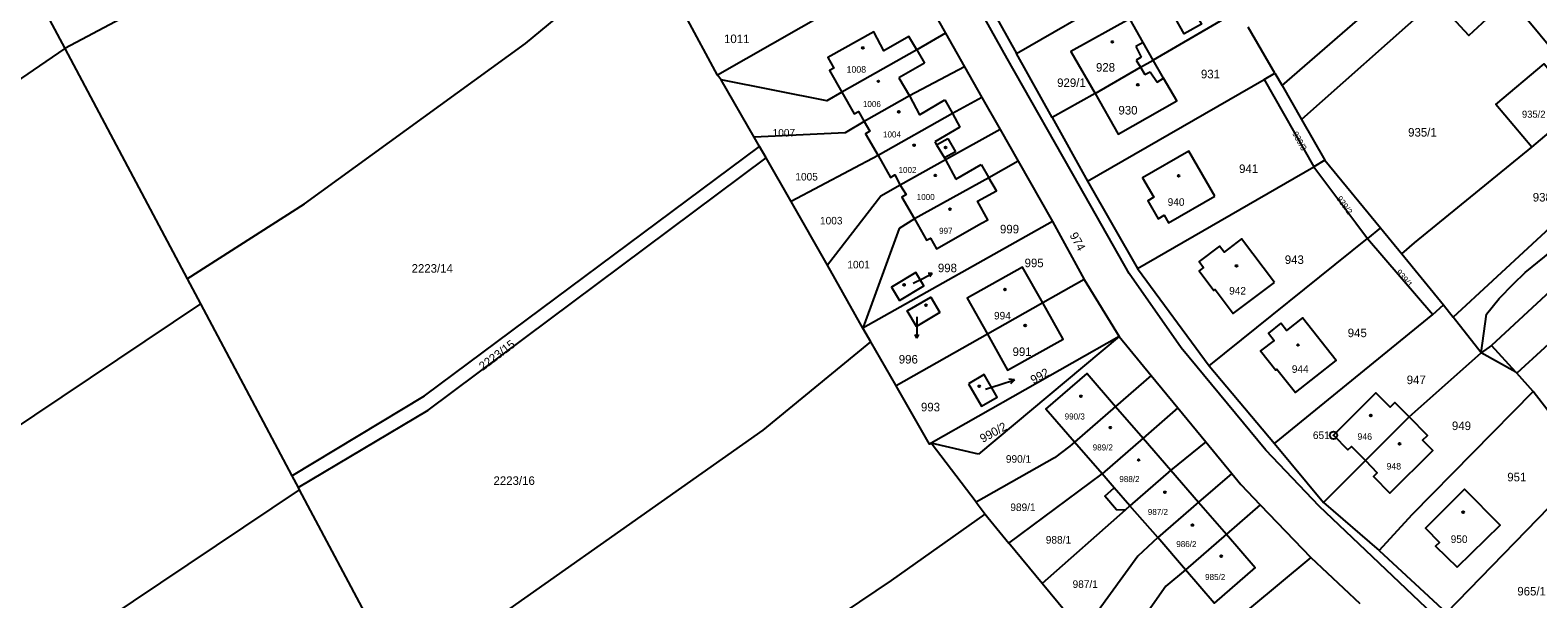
# Model space of a CAD drawing. Extents: x -504988 to -494607, y -1123820 to -1114018.
# Drawn here: x -497845.6 to -497545.8, y -1120241.9 to -1120128.9 of the extents above; entities that cross this region are included whole.
import ezdxf

# ---------------------------------------------------------------- set-up
doc = ezdxf.new("R2010")
doc.units = 0
for name, color, linetype in [('Hranice parcel', 7, 'Continuous'), ('Parcelní čísla', 7, 'Continuous'), ('Pop  PČ popisy', 7, 'Continuous'), ('Vnitřní kresba', 7, 'Continuous'), ('Značky bodu BP', 7, 'Continuous'), ('Značky budov', 7, 'Continuous')]:
    doc.layers.add(name, color=color, linetype=linetype)

msp = doc.modelspace()

# ---------------------------------------------------------------- linework, layer by layer
at = {"layer": 'Hranice parcel'}
for p, q in [((-497859.72, -1120093.09), (-497838.74, -1120132.52)), ((-497596.6, -1120139.88), (-497555.6, -1120104.26)), ((-497649.42, -1120133.52), (-497612.36, -1120112.05)), ((-497671.08, -1120116.23), (-497708.88, -1120137.79)), ((-497671.08, -1120116.23), (-497663.57, -1120129.44)), ((-497658.18, -1120117.79), (-497649.42, -1120133.52)), ((-497605.3, -1120124.94), (-497622.27, -1120134.79)), ((-497708.88, -1120137.79), (-497715.36, -1120125.87)), ((-497543.02, -1120132.55), (-497547.56, -1120127.17)), ((-497663.57, -1120129.44), (-497669.29, -1120132.77)), ((-497663.57, -1120129.44), (-497659.77, -1120136.14)), ((-497598.04, -1120137.4), (-497603.34, -1120128.29)), ((-497838.74, -1120132.52), (-497908.58, -1120180.24)), ((-497838.74, -1120132.52), (-497814.39, -1120178.27)), ((-497669.29, -1120132.77), (-497684.2, -1120141.18)), ((-497642.36, -1120146.19), (-497649.42, -1120133.52)), ((-497659.77, -1120136.14), (-497656.32, -1120142.22)), ((-497708.18, -1120138.71), (-497708.88, -1120137.79)), ((-497701.6, -1120150.15), (-497708.18, -1120138.71)), ((-497635.31, -1120158.85), (-497600.2, -1120138.64)), ((-497600.2, -1120138.64), (-497598.04, -1120137.4)), ((-497600.2, -1120138.64), (-497590.31, -1120156.01)), ((-497598.04, -1120137.4), (-497596.6, -1120139.88)), ((-497596.6, -1120139.88), (-497592.77, -1120146.58)), ((-497656.32, -1120142.22), (-497652.71, -1120148.57)), ((-497633.81, -1120141.47), (-497642.36, -1120146.19)), ((-497562.59, -1120185.87), (-497517.1, -1120143.77)), ((-497652.71, -1120148.57), (-497649.11, -1120154.91)), ((-497642.36, -1120146.19), (-497635.31, -1120158.85)), ((-497592.77, -1120146.58), (-497588.12, -1120154.71)), ((-497700.55, -1120151.98), (-497701.6, -1120150.15)), ((-497699.25, -1120154.24), (-497700.55, -1120151.98)), ((-497694.25, -1120162.93), (-497699.25, -1120154.24)), ((-497676.98, -1120153.77), (-497694.25, -1120162.93)), ((-497649.11, -1120154.91), (-497654.92, -1120158.19)), ((-497649.11, -1120154.91), (-497642.3, -1120166.91)), ((-497588.12, -1120154.71), (-497590.31, -1120156.01)), ((-497588.12, -1120154.71), (-497577.07, -1120168.16)), ((-497625.36, -1120176.21), (-497590.31, -1120156.01)), ((-497654.92, -1120158.19), (-497669.75, -1120166.36)), ((-497635.31, -1120158.85), (-497625.36, -1120176.21)), ((-497687.02, -1120175.53), (-497694.25, -1120162.93)), ((-497642.3, -1120166.91), (-497680, -1120188.05)), ((-497642.3, -1120166.91), (-497635.98, -1120178.4)), ((-497577.07, -1120168.16), (-497579.65, -1120170.24)), ((-497577.07, -1120168.16), (-497572.82, -1120173.32)), ((-497611.15, -1120195.58), (-497579.65, -1120170.24)), ((-497579.65, -1120170.24), (-497566.67, -1120185.37)), ((-497680, -1120188.05), (-497687.02, -1120175.53)), ((-497572.82, -1120173.32), (-497564.52, -1120183.42)), ((-497814.39, -1120178.27), (-497811.73, -1120183.27)), ((-497635.98, -1120178.4), (-497644.21, -1120183.07)), ((-497635.98, -1120178.4), (-497629.03, -1120189.75)), ((-497625.36, -1120176.21), (-497611.15, -1120195.58)), ((-497811.73, -1120183.27), (-497793.55, -1120217.43)), ((-497644.21, -1120183.07), (-497655.23, -1120189.26)), ((-497566.67, -1120185.37), (-497564.52, -1120183.42)), ((-497564.52, -1120183.42), (-497562.59, -1120185.87)), ((-497678.44, -1120190.76), (-497680, -1120188.05)), ((-497598.11, -1120210.96), (-497566.67, -1120185.37)), ((-497557.04, -1120192.95), (-497562.59, -1120185.87)), ((-497655.23, -1120189.26), (-497673.38, -1120199.54)), ((-497629.03, -1120189.75), (-497666.39, -1120210.9)), ((-497629.03, -1120189.75), (-497656.98, -1120213.09)), ((-497629.03, -1120189.75), (-497622.67, -1120197.47)), ((-497571.36, -1120205.7), (-497557.04, -1120192.95)), ((-497611.15, -1120195.58), (-497598.11, -1120210.96)), ((-497622.67, -1120197.47), (-497629.74, -1120203.61)), ((-497622.67, -1120197.47), (-497617.35, -1120203.93)), ((-497539.75, -1120209.69), (-497546.71, -1120200.63)), ((-497629.74, -1120203.61), (-497637.92, -1120210.71)), ((-497617.35, -1120203.93), (-497611.8, -1120210.67)), ((-497580.07, -1120214.37), (-497571.36, -1120205.7)), ((-497656.98, -1120213.09), (-497666.39, -1120210.9)), ((-497657.47, -1120222.62), (-497666.39, -1120210.9)), ((-497632.42, -1120217.03), (-497637.92, -1120210.71)), ((-497611.8, -1120210.67), (-497606.65, -1120216.92)), ((-497598.11, -1120210.96), (-497588.38, -1120222.72)), ((-497588.38, -1120222.72), (-497580.07, -1120214.37)), ((-497563.92, -1120244.66), (-497534.33, -1120214.13)), ((-497793.55, -1120217.43), (-497792.32, -1120219.73)), ((-497650.96, -1120230.76), (-497632.42, -1120217.03)), ((-497630.02, -1120219.8), (-497632.42, -1120217.03)), ((-497792.32, -1120219.73), (-497792.08, -1120220.19)), ((-497792.08, -1120220.19), (-497771.5, -1120258.84)), ((-497657.47, -1120222.62), (-497655.65, -1120225.01)), ((-497626.93, -1120223.36), (-497627.86, -1120224.24)), ((-497621.37, -1120229.68), (-497626.93, -1120223.36)), ((-497600.97, -1120223.17), (-497607.69, -1120229.01)), ((-497600.97, -1120223.17), (-497590.93, -1120233.65)), ((-497588.38, -1120222.72), (-497577.34, -1120232.28)), ((-497627.86, -1120224.24), (-497644.31, -1120238.83)), ((-497615.86, -1120236.11), (-497621.37, -1120229.68)), ((-497607.69, -1120229.01), (-497615.86, -1120236.11)), ((-497644.31, -1120238.83), (-497650.96, -1120230.76)), ((-497577.34, -1120232.28), (-497563.92, -1120244.66)), ((-497590.93, -1120233.65), (-497624.02, -1120261.1)), ((-497590.93, -1120233.65), (-497581.16, -1120242.79))]:
    msp.add_line(p, q, dxfattribs=at)
for points in [[(-497565.3, -1120246.14), (-497589.23, -1120223.42), (-497599.85, -1120212.32), (-497616.68, -1120192.01), (-497627.04, -1120177.2), (-497636.91, -1120159.82), (-497651.33, -1120134.51), (-497660.03, -1120118.82), (-497706.21, -1120037.1)], [(-497783.25, -1120099.15), (-497801, -1120111.8), (-497817.56, -1120121.27), (-497838.74, -1120132.52)], [(-497814.39, -1120178.27), (-497791.04, -1120163.39), (-497747.08, -1120131.51), (-497723.07, -1120111.62)], [(-497547.56, -1120127.17), (-497551.18, -1120123.12), (-497553.25, -1120124.98), (-497560.54, -1120117.05), (-497567.85, -1120123.76), (-497567.49, -1120124.21), (-497592.77, -1120146.58)], [(-497560.09, -1120118.82), (-497554.33, -1120125.13), (-497559.51, -1120129.92), (-497565.3, -1120123.6), (-497560.09, -1120118.82)], [(-497618.71, -1120125.01), (-497615.29, -1120123.05), (-497612.66, -1120127.65), (-497616.08, -1120129.6), (-497618.71, -1120125.01)], [(-497622.27, -1120134.79), (-497624.28, -1120131.33), (-497626.91, -1120126.6), (-497638.61, -1120133.1), (-497633.81, -1120141.47)], [(-497669.29, -1120132.77), (-497670.85, -1120130.15), (-497675.82, -1120132.95), (-497677.84, -1120129.17), (-497686.97, -1120134.26), (-497685.78, -1120136.38), (-497686.67, -1120136.87), (-497684.2, -1120141.18)], [(-497659.77, -1120136.14), (-497670.74, -1120141.93), (-497679.76, -1120146.99)], [(-497633.81, -1120141.47), (-497629.21, -1120149.5), (-497617.58, -1120142.9), (-497620.18, -1120138.41), (-497622.27, -1120134.79)], [(-497633.81, -1120141.47), (-497624.77, -1120136.24), (-497622.27, -1120134.79)], [(-497546.95, -1120152.13), (-497554.11, -1120143.64), (-497544.53, -1120135.56), (-497537.43, -1120143.98)], [(-497684.2, -1120141.18), (-497687.2, -1120142.9), (-497708.18, -1120138.71)], [(-497684.2, -1120141.18), (-497681.72, -1120145.51), (-497680.85, -1120145.02), (-497679.76, -1120146.99)], [(-497656.32, -1120142.22), (-497662.18, -1120145.44), (-497676.98, -1120153.77)], [(-497546.95, -1120152.13), (-497543.49, -1120149.17), (-497542.59, -1120150.19), (-497539, -1120147.11), (-497539.89, -1120146.08), (-497537.43, -1120143.98)], [(-497679.76, -1120146.99), (-497683.53, -1120149.27), (-497701.6, -1120150.15)], [(-497679.76, -1120146.99), (-497678.6, -1120148.94), (-497679.47, -1120149.43), (-497676.98, -1120153.77)], [(-497652.71, -1120148.57), (-497663.55, -1120154.65), (-497672.61, -1120159.67)], [(-497557.04, -1120192.95), (-497555.99, -1120185.32), (-497553.46, -1120182.17), (-497550.59, -1120179.26), (-497548.31, -1120177.01), (-497544.45, -1120173.92), (-497512.74, -1120147.57)], [(-497793.55, -1120217.43), (-497767.21, -1120201.53), (-497700.55, -1120151.98)], [(-497792.32, -1120219.73), (-497766.46, -1120204.39), (-497699.25, -1120154.24)], [(-497676.98, -1120153.77), (-497674.49, -1120158.11), (-497673.62, -1120157.61), (-497672.61, -1120159.67)], [(-497610.01, -1120161.84), (-497615.19, -1120152.88), (-497624.39, -1120158.19), (-497622.16, -1120162.06), (-497623.34, -1120162.74), (-497621.27, -1120166.33), (-497620.08, -1120165.64), (-497619.21, -1120167.16), (-497610.01, -1120161.84)], [(-497572.82, -1120173.32), (-497570.28, -1120171.09), (-497546.95, -1120152.13)], [(-497590.31, -1120156.01), (-497581.97, -1120167.13), (-497579.65, -1120170.24)], [(-497672.61, -1120159.67), (-497676.41, -1120161.85), (-497687.02, -1120175.53)], [(-497672.61, -1120159.67), (-497671.37, -1120161.53), (-497672.24, -1120162.03), (-497669.75, -1120166.36)], [(-497669.75, -1120166.36), (-497667.32, -1120170.6), (-497666.58, -1120170.17), (-497665.34, -1120172.33), (-497656.42, -1120167.19), (-497655.15, -1120166.55), (-497657.21, -1120162.85), (-497653.4, -1120160.79), (-497654.92, -1120158.19)], [(-497513.07, -1120167.22), (-497520.27, -1120159.36), (-497526.57, -1120165.21), (-497527.5, -1120164.21), (-497529.87, -1120166.41), (-497528.94, -1120167.41), (-497554.95, -1120191.54), (-497557.04, -1120192.95)], [(-497669.75, -1120166.36), (-497672.76, -1120168.24), (-497680, -1120188.05)], [(-497598.15, -1120179.02), (-497604.68, -1120170.34), (-497608.16, -1120172.96), (-497609.07, -1120171.75), (-497613.13, -1120174.81), (-497612.23, -1120176.02), (-497613.11, -1120176.68), (-497610.19, -1120180.56), (-497609.95, -1120180.38), (-497606.34, -1120185.18), (-497598.15, -1120179.02)], [(-497644.21, -1120183.07), (-497648.23, -1120175.92), (-497659.25, -1120182.11), (-497655.23, -1120189.26)], [(-497672.73, -1120182.58), (-497667.89, -1120179.67), (-497669.49, -1120177.01), (-497674.33, -1120179.92), (-497672.73, -1120182.58)], [(-497664.69, -1120184.98), (-497669.36, -1120187.73), (-497671.18, -1120184.64), (-497666.51, -1120181.89), (-497664.69, -1120184.98)], [(-497811.73, -1120183.27), (-497971.45, -1120290.23), (-498131.18, -1120397.19), (-498290.9, -1120504.16), (-498450.63, -1120611.12)], [(-497655.23, -1120189.26), (-497651.21, -1120196.43), (-497640.19, -1120190.24), (-497644.21, -1120183.07)], [(-497596.88, -1120187.11), (-497599.36, -1120189.07), (-497598.23, -1120190.49), (-497600.89, -1120192.59), (-497597.89, -1120196.39), (-497597.64, -1120196.19), (-497593.94, -1120200.88), (-497585.89, -1120194.52), (-497592.59, -1120186.03), (-497595.75, -1120188.53), (-497596.88, -1120187.11)], [(-497771.5, -1120258.84), (-497699.84, -1120208.32), (-497678.44, -1120190.76)], [(-497673.38, -1120199.54), (-497673.46, -1120199.4), (-497678.44, -1120190.76)], [(-497546.71, -1120200.63), (-497549.95, -1120197), (-497550.11, -1120196.82), (-497557.04, -1120192.95)], [(-497637.92, -1120210.71), (-497643.6, -1120204.16), (-497635.42, -1120197.06), (-497629.74, -1120203.61)], [(-497666.39, -1120210.9), (-497666.74, -1120211.1), (-497673.38, -1120199.54)], [(-497659, -1120199.1), (-497656.41, -1120203.57), (-497653.32, -1120201.78), (-497655.91, -1120197.31), (-497659, -1120199.1)], [(-497571.36, -1120205.7), (-497574.19, -1120202.81), (-497575.15, -1120203.76), (-497577.95, -1120200.91), (-497586.4, -1120209.35), (-497583.52, -1120212.26), (-497582.8, -1120211.56), (-497580.07, -1120214.37)], [(-497577.34, -1120232.28), (-497570.66, -1120225), (-497546.71, -1120200.63)], [(-497617.35, -1120203.93), (-497624.25, -1120209.93), (-497632.42, -1120217.03)], [(-497580.07, -1120214.37), (-497577.7, -1120216.82), (-497578.42, -1120217.52), (-497575.18, -1120220.86), (-497566.65, -1120212.41), (-497568.68, -1120210.35), (-497567.72, -1120209.41), (-497571.36, -1120205.7)], [(-497637.92, -1120210.71), (-497638.85, -1120211.53), (-497641.89, -1120213.84), (-497657.47, -1120222.62)], [(-497611.8, -1120210.67), (-497618.75, -1120216.26), (-497626.93, -1120223.36)], [(-497606.65, -1120216.92), (-497613.23, -1120222.62), (-497621.37, -1120229.68)], [(-497606.65, -1120216.92), (-497604.81, -1120219.16), (-497600.97, -1120223.17)], [(-497792.08, -1120220.19), (-497952.04, -1120327.31), (-498112, -1120434.42), (-498271.95, -1120541.54), (-498431.91, -1120648.66)], [(-497627.86, -1120224.24), (-497629.55, -1120224.17), (-497631.85, -1120221.45), (-497630.02, -1120219.8)], [(-497561.82, -1120235.58), (-497553.26, -1120227.23), (-497560.36, -1120220.09), (-497568.13, -1120227.82), (-497565.34, -1120230.63), (-497566.12, -1120231.41), (-497561.82, -1120235.58)], [(-497683.64, -1120244.47), (-497674.29, -1120238.2), (-497655.65, -1120225.01)], [(-497655.65, -1120225.01), (-497655.16, -1120225.66), (-497650.96, -1120230.76)], [(-497621.37, -1120229.68), (-497625.33, -1120233.35), (-497636.21, -1120248.36)], [(-497607.69, -1120229.01), (-497601.96, -1120235.61), (-497610.14, -1120242.71), (-497615.86, -1120236.11)], [(-497636.21, -1120248.36), (-497637.99, -1120246.5), (-497644.31, -1120238.83)], [(-497615.86, -1120236.11), (-497619.78, -1120239.34), (-497630.37, -1120254.46)]]:
    msp.add_lwpolyline(points, dxfattribs=at)
at = {"layer": 'Pop  PČ popisy'}
for p, q in [((-497669.98, -1120179.14), (-497668.1, -1120178.18)), ((-497668.1, -1120178.18), (-497666.23, -1120177.23)), ((-497666.23, -1120177.23), (-497667.01, -1120177.23)), ((-497666.23, -1120177.23), (-497666.69, -1120177.86)), ((-497669.25, -1120185.85), (-497669.25, -1120187.95)), ((-497669.25, -1120187.95), (-497669.25, -1120190.05)), ((-497669.25, -1120190.05), (-497669.6, -1120189.35)), ((-497669.25, -1120190.05), (-497668.9, -1120189.35)), ((-497655.58, -1120200.21), (-497652.72, -1120199.28)), ((-497652.72, -1120199.28), (-497649.87, -1120198.35)), ((-497649.87, -1120198.35), (-497650.97, -1120198.19)), ((-497649.87, -1120198.35), (-497650.66, -1120199.14))]:
    msp.add_line(p, q, dxfattribs=at)
at = {"layer": 'Vnitřní kresba'}
for p, q in [((-497669.29, -1120132.77), (-497667.72, -1120135.39)), ((-497624.28, -1120131.33), (-497625.72, -1120132.1)), ((-497625.72, -1120132.1), (-497624.63, -1120134.2)), ((-497667.72, -1120135.39), (-497672.85, -1120138.33)), ((-497624.63, -1120134.2), (-497625.64, -1120134.8)), ((-497625.64, -1120134.8), (-497624.77, -1120136.24)), ((-497624.77, -1120136.24), (-497623.9, -1120137.67)), ((-497672.85, -1120138.33), (-497670.74, -1120141.93)), ((-497623.9, -1120137.67), (-497622.83, -1120137.11)), ((-497622.83, -1120137.11), (-497621.47, -1120139.21)), ((-497621.47, -1120139.21), (-497620.18, -1120138.41)), ((-497670.74, -1120141.93), (-497668.77, -1120145.69)), ((-497668.77, -1120145.69), (-497663.67, -1120142.72)), ((-497663.67, -1120142.72), (-497662.18, -1120145.44)), ((-497662.18, -1120145.44), (-497660.69, -1120148.15)), ((-497660.69, -1120148.15), (-497665.68, -1120151.02)), ((-497665.68, -1120151.02), (-497665.33, -1120151.62)), ((-497665.33, -1120151.62), (-497663.08, -1120150.4)), ((-497665.33, -1120151.62), (-497663.78, -1120154.25)), ((-497663.08, -1120150.4), (-497661.61, -1120153.03)), ((-497661.61, -1120153.03), (-497663.78, -1120154.25)), ((-497663.78, -1120154.25), (-497663.55, -1120154.65)), ((-497663.55, -1120154.65), (-497661.5, -1120158.44)), ((-497661.5, -1120158.44), (-497656.45, -1120155.56)), ((-497656.45, -1120155.56), (-497654.92, -1120158.19)), ((-497538.48, -1120186.5), (-497549.95, -1120197)), ((-497550.11, -1120196.82), (-497554.95, -1120191.54)), ((-497629.74, -1120203.61), (-497624.25, -1120209.93)), ((-497624.25, -1120209.93), (-497618.75, -1120216.26)), ((-497618.75, -1120216.26), (-497613.23, -1120222.62)), ((-497626.93, -1120223.36), (-497630.02, -1120219.8)), ((-497613.23, -1120222.62), (-497607.69, -1120229.01))]:
    msp.add_line(p, q, dxfattribs=at)
at = {"layer": 'Značky bodu BP'}
for radius in [0.75, 0.03]:
    msp.add_circle((-497586.4, -1120209.35), radius, dxfattribs=at)
at = {"layer": 'Značky budov'}
for centre in [(-497630.39, -1120131.19), (-497680.01, -1120132.39), (-497676.92, -1120139.03), (-497625.31, -1120139.71), (-497672.86, -1120145.08), (-497669.81, -1120151.72), (-497663.55, -1120152.17), (-497665.59, -1120157.72), (-497617.2, -1120157.81), (-497662.68, -1120164.42), (-497605.7, -1120175.7), (-497671.8, -1120179.47), (-497651.74, -1120180.39), (-497667.45, -1120183.5), (-497647.72, -1120187.55), (-497593.47, -1120191.41), (-497656.86, -1120199.62), (-497636.64, -1120201.6), (-497579, -1120205.43), (-497630.79, -1120207.83), (-497573.26, -1120211.06), (-497625.15, -1120214.26), (-497619.93, -1120220.68), (-497614.46, -1120227.2), (-497560.62, -1120224.64), (-497608.73, -1120233.37)]:
    msp.add_circle(centre, 0.175, dxfattribs=at)

# ---------------------------------------------------------------- texts
at = {"layer": 'Parcelní čísla'}
for s, height, p in [('1011', 1.7, (-497707.62, -1120131.43)), ('1008', 1.3, (-497683.23, -1120137.31)), ('928', 1.7, (-497633.64, -1120137.1)), ('931', 1.7, (-497612.77, -1120138.43)), ('929/1', 1.7, (-497641.36, -1120140.15)), ('1006', 1.2, (-497679.99, -1120144.14)), ('930', 1.7, (-497629.17, -1120145.62)), ('935/2', 1.4, (-497548.92, -1120146.26)), ('1007', 1.5, (-497697.95, -1120150)), ('1004', 1.2, (-497676, -1120150.18)), ('935/1', 1.7, (-497571.56, -1120150)), ('1005', 1.5, (-497693.42, -1120158.73)), ('1002', 1.2, (-497672.91, -1120157.24)), ('941', 1.7, (-497605.18, -1120157.24)), ('1000', 1.2, (-497669.29, -1120162.61)), ('940', 1.5, (-497619.38, -1120163.76)), ('938', 1.7, (-497546.77, -1120162.91)), ('1003', 1.5, (-497688.52, -1120167.46)), ('997', 1.2, (-497664.84, -1120169.33)), ('999', 1.7, (-497652.73, -1120169.24)), ('2223/14', 1.7, (-497769.75, -1120177.05)), ('1001', 1.5, (-497683.08, -1120176.19)), ('998', 1.7, (-497665.08, -1120176.96)), ('995', 1.7, (-497647.84, -1120175.96)), ('943', 1.7, (-497596.09, -1120175.31)), ('942', 1.5, (-497607.15, -1120181.39)), ('994', 1.5, (-497653.92, -1120186.34)), ('945', 1.7, (-497583.57, -1120189.86)), ('996', 1.7, (-497672.86, -1120195.1)), ('991', 1.7, (-497650.23, -1120193.6)), ('944', 1.5, (-497594.69, -1120196.95)), ('947', 1.7, (-497571.84, -1120199.19)), ('993', 1.7, (-497668.45, -1120204.6)), ('990/3', 1.2, (-497639.87, -1120206.22)), ('946', 1.3, (-497581.64, -1120210.26)), ('949', 1.7, (-497562.85, -1120208.32)), ('989/2', 1.2, (-497634.29, -1120212.37)), ('990/1', 1.5, (-497651.56, -1120214.81)), ('948', 1.3, (-497575.86, -1120216.16)), ('2223/16', 1.7, (-497753.46, -1120219.22)), ('988/2', 1.2, (-497628.99, -1120218.66)), ('951', 1.7, (-497551.84, -1120218.51)), ('989/1', 1.5, (-497650.67, -1120224.41)), ('987/2', 1.2, (-497623.33, -1120225.19)), ('988/1', 1.5, (-497643.62, -1120230.88)), ('950', 1.5, (-497563.09, -1120230.75)), ('986/2', 1.2, (-497617.67, -1120231.57)), ('987/1', 1.5, (-497638.29, -1120239.68)), ('985/2', 1.2, (-497611.94, -1120238.11)), ('965/1', 1.7, (-497549.84, -1120241.19))]:
    msp.add_text(s, height=height, dxfattribs=at).set_placement(p)
for s, height, rotation, p in [('939/3', 1.2, 299, (-497594.64, -1120149.41)), ('939/2', 1.2, 306, (-497585.86, -1120162.35)), ('974', 1.7, 299, (-497638.96, -1120169.6)), ('939/1', 1.2, 310, (-497574.05, -1120177.02)), ('2223/15', 1.7, 37, (-497755.56, -1120196.57)), ('992', 1.7, 29, (-497646.08, -1120199.23)), ('990/2', 1.7, 29, (-497656.15, -1120210.9))]:
    msp.add_text(s, height=height, rotation=rotation, dxfattribs=at).set_placement(p)
at = {"layer": 'Značky bodu BP'}
msp.add_text('651', height=1.5, dxfattribs=at).set_placement((-497590.5, -1120210.1))

doc.saveas('drawing.dxf')
